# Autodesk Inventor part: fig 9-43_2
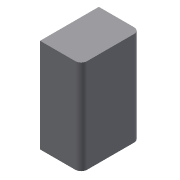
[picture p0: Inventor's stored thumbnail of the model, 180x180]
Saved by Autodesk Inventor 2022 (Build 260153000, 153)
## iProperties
Created: 2013-03
Part Number: fig 9-43_2
Material: Generic
Document SubType Name: Modeling
Designer: CADCIM
Density: 1 g/cm^3
Appearance: Default
Author: CADCIM
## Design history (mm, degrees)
sketch "Sketch1"
  geometry: L1 (-2.508, 1.862)-(2.492, 1.862); L2 (2.492, 1.862)-(2.492, -6.138); L3 (2.492, -6.138)-(-2.508, -6.138); L4 (-2.508, -6.138)-(-2.508, 1.862); 1 further point
  constraints: 8 end point, 2 parallel, 1 horizontal, 1 perpendicular
  dimensions: "d0" = 5 distance of L1.start L1.end; "d2" = 8 distance of L1.end L2.end
extrude "Extrusion1" new body sketch "Sketch1" distance "d3" = 3.5; taper "d4" = 0 deg
fillet "Fillet1" dims "d5" = 0.5
fillet "Fillet2" dims "d6" = 0.5
body "Solid1"
